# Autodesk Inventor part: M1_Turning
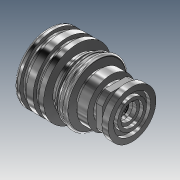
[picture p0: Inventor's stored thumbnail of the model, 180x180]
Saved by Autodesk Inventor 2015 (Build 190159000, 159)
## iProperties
Created: 2015-04
Part Number: M1_Turning
Material: Aço
Document SubType Name: Modeling
Designer: Andrew Almeida
Density: 7.85 g/cm^3
Appearance: Cromo - Polido
Title: C:/Users/Andrew Almeida/Documents/Projeto WS2015/WS2015 CAD Data ANLAS/06/#06 - CNC Turning/01 - 3D Models/M1_Turning.stp
Creation Date: 2015-04-23
Sending System: Autodesk Translation Framework v4.0.0.5211
Preprocessor: ST-DEVELOPER v16.1
Author: Andrew Almeida
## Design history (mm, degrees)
node "M1_Turning1"
feature "Rosca1" dims "d0" = 10, "d1" = 0
sketch "Esboço2"
  geometry: L1 (9.25, 0)-(9.25, 15.182); L2 (9.25, 15.182)-(8.509, 15.182); L3 (8.509, 15.182)-(8.509, 0); L4 (8.509, 0)-(9.25, 0); L5 (0, -114.839)-(0, 53.161) reference
  constraints: 8 end point
revolve "Revolução1" sketch "Esboço2" stored, may be unused: angle "d11" = 0 deg
sketch "Esboço1"
  geometry: L1 (-0.583, -0.051)-(-0.5, -0.051); L2 (0.083, -0.691)-(0, -0.851); L3 (-1, -0.851)-(-1.083, -0.691); L4 (-0.417, -0.051)-(-0.5, 0.109); L5 (-0.5, 0.109)-(-0.583, -0.051); L6 (-1, -0.851)-(-0.917, -0.691); L7 (-0.417, -0.051)-(-0.083, -0.691); L8 (-1.083, -0.691)-(-0.917, -0.691); L9 (0.083, -0.691)-(-0.083, -0.691); L10 (-1, -0.851)-(-1, -0.691); L11 (0, -0.851)-(0, -0.691); L12 (-0.5, 0.109)-(-0.5, 0); L13 (-1, -0.742)-(0, -0.742); L14 (-0.083, -0.691)-(0, -0.851); L15 (-0.917, -0.691)-(-0.583, -0.051); L16 (0, 0)-(0, 0.018); L17 (0, 0.018)-(0, 0); L18 (0, 0)-(0.033, 0); L19 (-0.5, 0)-(-0.5, -0.051); L20 (-0.5, -0.051)-(-0.417, -0.051); A1 r 0.094 centre (-1, -0.648) between (-1.083, -0.691) and (-1, -0.742); A2 r 0.094 centre (-1, -0.648) between (-1, -0.742) and (-0.917, -0.691); A3 r 0.094 centre (0, -0.648) between (-0.083, -0.691) and (0, -0.742); A4 r 0.094 centre (0, -0.648) between (0, -0.742) and (0.083, -0.691); A5 r 0.094 centre (-0.5, -0.094) between (-0.5, 0) and (-0.583, -0.051); A6 r 0.094 centre (-0.5, -0.094) between (-0.417, -0.051) and (-0.5, 0)
  constraints: 40 end point, 12 point on circle, 10 parallel, 8 tangent, 6 centre point, 6 collinear, 2 midpoint, 2 point on line, 1 horizontal, 1 perpendicular, 3 other
  dimensions: "d2" = 55 deg angle of L7 L15 (= d9); "d3" = 0.16008 distance of L4.end L1.end (= 0.160083 x Esboço1_Pitch); "d4" = 0.16008 distance of L2.end L11.end (= 0.160083 x Esboço1_Pitch); "Esboço1_ThreadOffset" = 0 distance between parallel lines of L16 L11; "Esboço1_MajorRadius" = 0.74146 distance from line of L13 L16.start; "d7" = 1 distance from line of L2.end L10 (= Esboço1_Pitch); "Esboço1_MinorRadius" = 0 distance edge to line of A6 L18 (derived)
feature "Espiral1" sketch "Esboço1" pitch "d12" = 1.5015; turns "d14" = 1; dims "d13" = 18.18152, "d15" = 0, angle "d16" = 0 deg, angle "d17" = 0 deg, "d18" = 0, "d19" = 0
node "Body1"
node "Base1"
node "Sólido2"
other parameters: "d9" = 55 deg [user parameter; used in 1 equation term], "Esboço1_Pitch" = 1 [user parameter; used in 3 equation terms]
